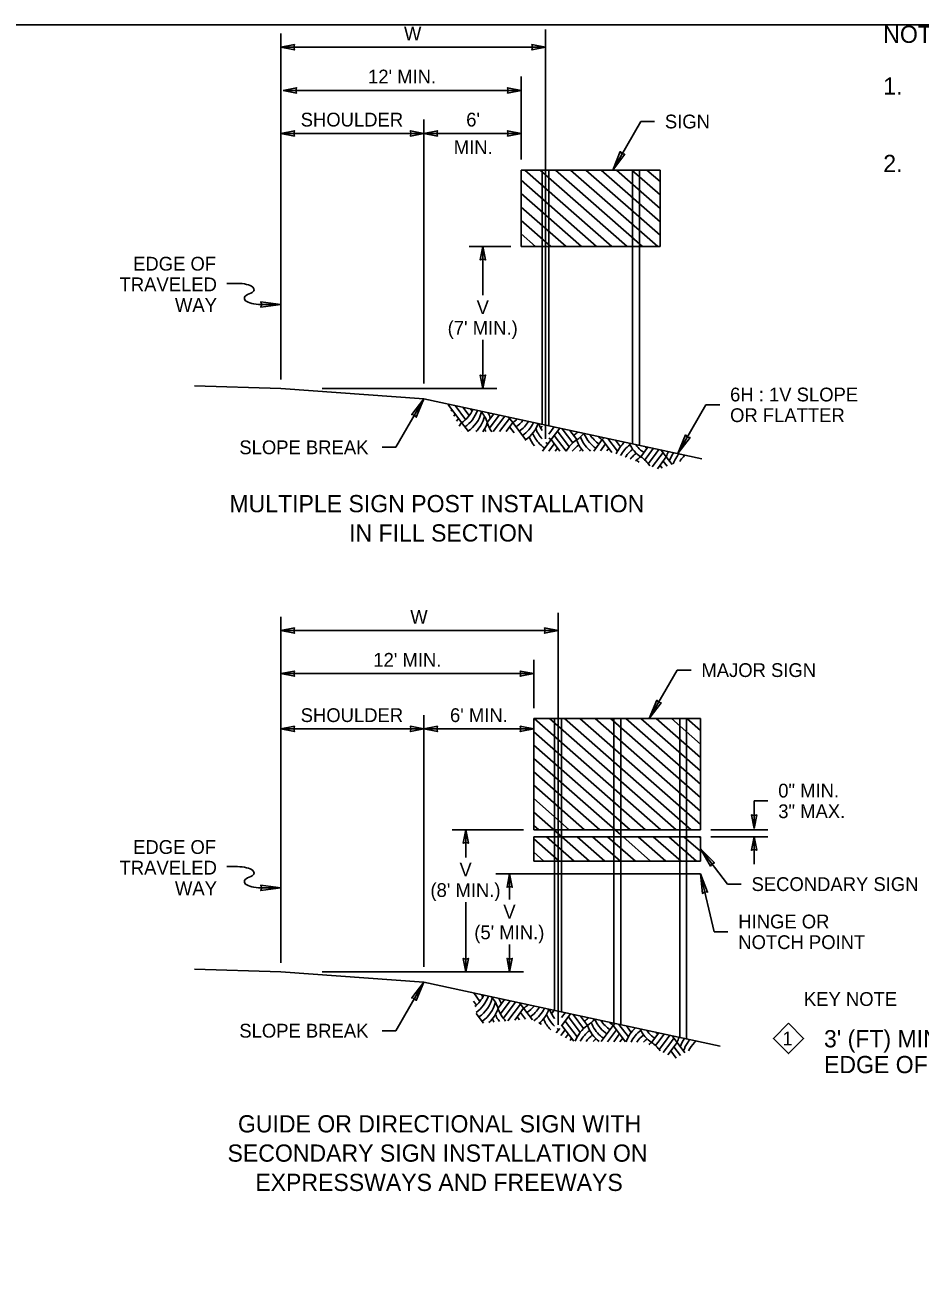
# Model space of a CAD drawing. Extents: x 99862 to 104211, y 98939 to 102076.
# Drawn here: x 101570 to 102609, y 100631 to 102076 of the extents above; entities that cross this region are included whole.
import ezdxf

# ---------------------------------------------------------------- set-up
doc = ezdxf.new("R2010")
doc.units = 0
for name, color, linetype in [('Level 1', 7, 'Continuous'), ('Level 14', 7, 'Continuous'), ('Level 15', 7, 'Continuous'), ('Level 2', 7, 'Continuous'), ('Level 20', 7, 'Continuous'), ('Level 6', 7, 'Continuous')]:
    doc.layers.add(name, color=color, linetype=linetype)

msp = doc.modelspace()

# ---------------------------------------------------------------- linework, layer by layer
at = {"layer": 'Level 1'}
msp.add_lwpolyline([(99862, 99999.5), (103151, 99999.5), (103151, 102075.5), (99862, 102075.5)], close=True, dxfattribs=at)
msp.add_lwpolyline([(99862, 99999.5), (103151, 99999.5), (103151, 102075.5), (99862, 102075.5)], close=True, dxfattribs=at)
at = {"layer": 'Level 14'}
for p, q in [((101816.5, 101775.4), (101804.3, 101775.4)), ((101863, 101750.8), (101843.8, 101750.8)), ((101816.5, 101098.1), (101804.3, 101098.1)), ((101863, 101073.5), (101843.8, 101073.5))]:
    msp.add_line(p, q, dxfattribs=at)
for points in [[(101867.1, 101750.8), (101843.7, 101747.8), (101844.8, 101750.8), (101843.7, 101753.9)], [(101867.1, 101073.5), (101843.7, 101070.4), (101844.8, 101073.5), (101843.7, 101076.5)]]:
    msp.add_lwpolyline(points, close=True, dxfattribs=at)
for centre, start_param, end_param in [((101816.7, 101768.2), 5.497747, 7.861127), ((101843.8, 101758), 2.356226, 4.712389), ((101816.7, 101090.9), 5.497747, 7.861127), ((101843.8, 101080.7), 2.356226, 4.712389)]:
    msp.add_ellipse(centre, major_axis=(19.2, 0), ratio=0.375, start_param=start_param, end_param=end_param, dxfattribs=at)
at = {"layer": 'Level 15'}
for p, q in [((101867.1, 102065.5), (101867.1, 101663.8)), ((102174.2, 102049.5), (101867.1, 102049.5)), ((102145.9, 102015.5), (102145.9, 101919)), ((102145.9, 101999.5), (101869.5, 101999.5)), ((102033, 101965.5), (102033, 101659.1)), ((102252.2, 101907), (102284.7, 101963.3)), ((102284.7, 101963.3), (102300.7, 101963.3)), ((102033, 101949.5), (101867.1, 101949.5)), ((102145.9, 101949.5), (102033, 101949.5)), ((102085.6, 101818.3), (102133.9, 101818.3)), ((102101.6, 101818.3), (102101.6, 101761.7)), ((102101.6, 101709.7), (102101.6, 101653.1)), ((101915.1, 101653.1), (102117.6, 101653.1)), ((102033, 101641.3), (102000.5, 101585)), ((102327.9, 101578), (102360.4, 101634.3)), ((102360.4, 101634.3), (102376.4, 101634.3)), ((101984.5, 101585), (102000.5, 101585)), ((101867.1, 101388.2), (101867.1, 100986.5)), ((102188.8, 101372.2), (101867.1, 101372.2)), ((102160.5, 101338.2), (102160.5, 101282)), ((102160.5, 101322.2), (101867.1, 101322.2)), ((102294.6, 101270), (102327.1, 101326.3)), ((102327.1, 101326.3), (102343.1, 101326.3)), ((102033, 101274), (102033, 100981.8)), ((102033, 101258), (101867.1, 101258)), ((102160.5, 101258), (102033, 101258)), ((102416.3, 101142.4), (102416.3, 101174.4)), ((102416.3, 101174.4), (102432.3, 101174.4)), ((102065.7, 101140.9), (102148.5, 101140.9)), ((102081.7, 101140.9), (102081.7, 101108.9)), ((102366.1, 101140.9), (102432.3, 101140.9)), ((102366.1, 101132.9), (102432.3, 101132.9)), ((102416.3, 101100.9), (102416.3, 101132.9)), ((102385.3, 101077.8), (102354.1, 101118.8)), ((102132.5, 101089.9), (102132.5, 101059.8)), ((102369.9, 101022.4), (102354, 101089.9)), ((102385.3, 101077.8), (102401.3, 101077.8)), ((102081.7, 101056.9), (102081.7, 100975.8)), ((102369.9, 101022.4), (102385.9, 101022.4)), ((102132.5, 101007.8), (102132.5, 100975.8)), ((101915.1, 100975.8), (102148.5, 100975.8)), ((102033, 100963.9), (102000.5, 100907.6)), ((101984.5, 100907.6), (102000.5, 100907.6))]:
    msp.add_line(p, q, dxfattribs=at)
for points in [[(101867.1, 102049.5), (101882.8, 102046.4), (101882.1, 102049.5), (101882.8, 102052.6)], [(102174.2, 102049.5), (102158.4, 102046.4), (102159.2, 102049.5), (102158.4, 102052.6)], [(101869.5, 101999.5), (101885.2, 101996.4), (101884.5, 101999.5), (101885.2, 102002.6)], [(102145.9, 101999.5), (102130.2, 101996.4), (102130.9, 101999.5), (102130.2, 102002.6)], [(101867.1, 101949.5), (101882.8, 101946.4), (101882.1, 101949.5), (101882.8, 101952.6)], [(102033, 101949.5), (102017.3, 101946.4), (102018, 101949.5), (102017.3, 101952.6)], [(102033, 101949.5), (102048.7, 101946.4), (102048, 101949.5), (102048.7, 101952.6)], [(102145.9, 101949.5), (102130.2, 101946.4), (102130.9, 101949.5), (102130.2, 101952.6)], [(102252.2, 101907), (102261, 101928.3), (102263.1, 101925.9), (102266.2, 101925.3)], [(102101.6, 101818.3), (102098.5, 101802.6), (102101.6, 101803.3), (102104.7, 101802.6)], [(102101.6, 101653.1), (102098.5, 101668.8), (102101.6, 101668.1), (102104.7, 101668.8)], [(102033, 101641.3), (102024.2, 101620), (102022.1, 101622.4), (102019, 101623)], [(102327.9, 101578), (102336.7, 101599.3), (102338.8, 101596.9), (102341.9, 101596.3)], [(101867.1, 101372.2), (101882.8, 101369.1), (101882.1, 101372.2), (101882.8, 101375.2)], [(102188.8, 101372.2), (102173.1, 101369.1), (102173.8, 101372.2), (102173.1, 101375.2)], [(101867.1, 101322.2), (101882.8, 101319.1), (101882.1, 101322.2), (101882.8, 101325.2)], [(102160.5, 101322.2), (102144.8, 101319.1), (102145.5, 101322.2), (102144.8, 101325.2)], [(102294.6, 101270), (102303.4, 101291.3), (102305.5, 101288.9), (102308.6, 101288.3)], [(101867.1, 101258), (101882.8, 101254.9), (101882.1, 101258), (101882.8, 101261.1)], [(102033, 101258), (102017.3, 101254.9), (102018, 101258), (102017.3, 101261.1)], [(102033, 101258), (102048.7, 101254.9), (102048, 101258), (102048.7, 101261.1)], [(102160.5, 101258), (102144.8, 101254.9), (102145.5, 101258), (102144.8, 101261.1)], [(102416.3, 101142.4), (102413.2, 101158.2), (102416.3, 101157.4), (102419.4, 101158.2)], [(102081.7, 101140.9), (102078.6, 101125.2), (102081.7, 101126), (102084.7, 101125.2)], [(102416.3, 101132.9), (102413.2, 101117.2), (102416.3, 101117.9), (102419.4, 101117.2)], [(102354.1, 101118.8), (102365.6, 101098.8), (102367.3, 101101.4), (102370.3, 101102.4)], [(102132.5, 101089.9), (102129.5, 101074.2), (102132.5, 101074.9), (102135.6, 101074.2)], [(102354, 101089.9), (102356.3, 101067), (102359, 101068.7), (102362.2, 101068.4)], [(102081.7, 100975.8), (102078.6, 100991.5), (102081.7, 100990.8), (102084.7, 100991.5)], [(102132.5, 100975.8), (102129.5, 100991.5), (102132.5, 100990.8), (102135.6, 100991.5)], [(102033, 100963.9), (102024.2, 100942.7), (102022.1, 100945.1), (102019, 100945.6)]]:
    msp.add_lwpolyline(points, close=True, dxfattribs=at)
at = {"layer": 'Level 2'}
for p, q in [((102174.2, 102070.3), (102174.2, 101594.8)), ((102145.9, 101907), (102145.9, 101818.3)), ((102145.9, 101907), (102307.3, 101907)), ((102251.2, 101818.3), (102150.1, 101907)), ((102268.9, 101818.3), (102167.8, 101907)), ((102170.1, 101818.3), (102170.1, 101907)), ((102178.2, 101818.3), (102178.2, 101907)), ((102286.6, 101818.3), (102185.6, 101907)), ((102304.4, 101818.3), (102203.3, 101907)), ((102307.3, 101831.3), (102221, 101907)), ((102307.3, 101846.9), (102238.7, 101907)), ((102307.3, 101862.4), (102256.5, 101907)), ((102307.3, 101878), (102274.2, 101907)), ((102275, 101818.3), (102275, 101907)), ((102283.1, 101818.3), (102283.1, 101907)), ((102307.3, 101893.5), (102291.9, 101907)), ((102307.3, 101907), (102307.3, 101818.3)), ((102233.5, 101818.3), (102145.9, 101895.1)), ((102215.8, 101818.3), (102145.9, 101879.6)), ((102198.1, 101818.3), (102145.9, 101864)), ((102180.3, 101818.3), (102145.9, 101848.5)), ((102162.6, 101818.3), (102145.9, 101832.9)), ((102145.9, 101818.3), (102307.3, 101818.3)), ((102170.1, 101818.3), (102170.1, 101611.6)), ((102178.2, 101818.3), (102178.2, 101609.9)), ((102275, 101818.3), (102275, 101589)), ((102283.1, 101818.3), (102283.1, 101587.2)), ((101867.1, 101653.1), (101766.6, 101656.2)), ((101867.1, 101653.1), (102033, 101641.3)), ((102033, 101641.3), (102355.7, 101571.5)), ((102275.5, 101588.9), (102275, 101589.3)), ((102188.8, 101393), (102188.8, 100914.3)), ((102160.5, 101270), (102160.5, 101140.9)), ((102160.5, 101270), (102354.1, 101270)), ((102308, 101140.9), (102161, 101270)), ((102325.7, 101140.9), (102178.7, 101270)), ((102184.7, 101140.9), (102184.7, 101270)), ((102192.8, 101140.9), (102192.8, 101270)), ((102343.4, 101140.9), (102196.4, 101270)), ((102354.1, 101147.1), (102214.1, 101270)), ((102354.1, 101162.7), (102231.9, 101270)), ((102354.1, 101178.2), (102249.6, 101270)), ((102253.3, 101140.9), (102253.3, 101270)), ((102261.4, 101140.9), (102261.4, 101270)), ((102354.1, 101193.8), (102267.3, 101270)), ((102354.1, 101209.3), (102285, 101270)), ((102354.1, 101224.9), (102302.7, 101270)), ((102354.1, 101240.4), (102320.5, 101270)), ((102329.9, 101140.9), (102329.9, 101270)), ((102338, 101140.9), (102338, 101270)), ((102354.1, 101256), (102338.2, 101270)), ((102354.1, 101270), (102354.1, 101140.9)), ((102290.3, 101140.9), (102160.5, 101254.8)), ((102272.6, 101140.9), (102160.5, 101239.3)), ((102261.4, 101135.2), (102160.5, 101223.7)), ((102237.1, 101140.9), (102160.5, 101208.2)), ((102219.4, 101140.9), (102160.5, 101192.6)), ((102160.5, 101177.1), (102201.7, 101140.9)), ((102225.3, 101104.6), (102160.8, 101161.3)), ((102166.3, 101140.9), (102160.5, 101146)), ((102160.5, 101140.9), (102354.1, 101140.9)), ((102160.5, 101132.9), (102354.1, 101132.9)), ((102160.5, 101132.9), (102160.5, 101104.6)), ((102207.6, 101104.6), (102175.5, 101132.9)), ((102184.7, 101140.9), (102184.7, 101132.9)), ((102184.7, 101132.9), (102184.7, 101104.6)), ((102192.8, 101140.9), (102192.8, 101132.9)), ((102192.8, 101132.9), (102192.8, 101104.6)), ((102210.9, 101132.9), (102243, 101104.6)), ((102261.4, 101104.1), (102228.6, 101132.9)), ((102278.5, 101104.6), (102246.3, 101132.9)), ((102253.3, 101140.9), (102253.3, 101132.9)), ((102253.3, 101132.9), (102253.3, 101104.6)), ((102261.4, 101140.9), (102261.4, 101132.9)), ((102261.4, 101132.9), (102261.4, 101104.6)), ((102296.2, 101104.6), (102263.9, 101133)), ((102313.9, 101104.6), (102281.7, 101132.9)), ((102331.5, 101104.6), (102299.3, 101132.9)), ((102349.3, 101104.6), (102317.2, 101132.9)), ((102329.9, 101132.9), (102329.9, 101140.9)), ((102329.9, 101132.9), (102329.9, 101104.6)), ((102354.1, 101116), (102334.9, 101132.9)), ((102338, 101132.9), (102338, 101140.9)), ((102338, 101132.9), (102338, 101104.6)), ((102354.1, 101131.6), (102352.6, 101132.9)), ((102354.1, 101132.9), (102354.1, 101104.6)), ((102189.9, 101104.6), (102160.5, 101130.4)), ((102172.2, 101104.6), (102160.5, 101114.8)), ((102160.5, 101104.6), (102354.1, 101104.6)), ((102184.7, 101104.6), (102184.7, 100931.1)), ((102192.8, 101104.6), (102192.8, 100929.4)), ((102253.3, 101104.6), (102253.3, 100916.3)), ((102261.4, 101104.6), (102261.4, 100914.6)), ((102329.9, 100899.8), (102329.9, 101104.6)), ((102338, 100898), (102338, 101104.6)), ((102116.5, 101089.9), (102354, 101089.9)), ((101867.1, 100975.8), (101766.6, 100978.9)), ((101867.1, 100975.8), (102033, 100963.9)), ((102033, 100963.9), (102377, 100889.6))]:
    msp.add_line(p, q, dxfattribs=at)
msp.add_lwpolyline([(102033, 101641.3), (102031.2, 101639.4), (102031.7, 101639.2), (102032, 101638.9)], close=True, dxfattribs=at)
at = {"layer": 'Level 20'}
msp.add_lwpolyline([(102456.2, 100916.2), (102473.7, 100898.6), (102456.2, 100881.1), (102438.6, 100898.6)], close=True, dxfattribs=at)
at = {"layer": 'Level 6'}
for p, q in [((102061.4, 101632.8), (102061.9, 101633.5)), ((102061.9, 101633.5), (102062.9, 101634.8)), ((102061.9, 101633.5), (102076.8, 101613.7)), ((102064.5, 101627), (102065.6, 101628.5)), ((102067.6, 101621.2), (102069.4, 101623.6)), ((102069.4, 101633.4), (102081.4, 101617.3)), ((102078.3, 101631.5), (102085.5, 101621.8)), ((102087.1, 101629.6), (102089, 101627.1)), ((102106.5, 101613.7), (102114.1, 101623.8)), ((102109.2, 101607.3), (102120.4, 101622.4)), ((102070.7, 101615.4), (102073.1, 101618.6)), ((102073.8, 101609.6), (102076.8, 101613.7)), ((102076.8, 101613.7), (102084.6, 101603.2)), ((102113.5, 101603.2), (102126.8, 101621)), ((102120.9, 101603.2), (102132.5, 101618.6)), ((102128.4, 101603.2), (102136.2, 101613.7)), ((102131.4, 101620), (102136.2, 101613.7)), ((102132.5, 101608.7), (102137.6, 101601.9)), ((102136.2, 101613.7), (102151, 101593.9)), ((102140.3, 101618.1), (102140.8, 101617.3)), ((102168.5, 101607.3), (102170.2, 101609.5)), ((102178.2, 101600.3), (102184.3, 101608.6)), ((102077.1, 101603.3), (102077.2, 101603.2)), ((102128.8, 101603.8), (102129.2, 101603.2)), ((102170.7, 101580.5), (102180.7, 101593.9)), ((102180.7, 101593.9), (102190.7, 101607.2)), ((102180.7, 101593.9), (102190.7, 101580.5)), ((102184.4, 101598.8), (102198.1, 101580.5)), ((102188.1, 101603.8), (102201.7, 101585.7)), ((102193.4, 101606.6), (102205.8, 101590.2)), ((102202.3, 101604.7), (102210.4, 101593.9)), ((102230.3, 101580.7), (102240.1, 101593.9)), ((102240.1, 101593.9), (102241.8, 101596.1)), ((102240.1, 101593.9), (102251.3, 101578.9)), ((102246.6, 101595.1), (102257.6, 101580.4)), ((102255.5, 101593.2), (102261.1, 101585.7)), ((102178.1, 101580.4), (102184.4, 101588.9)), ((102185.5, 101580.5), (102188.1, 101584)), ((102237.8, 101580.8), (102243.8, 101588.9)), ((102245.2, 101580.8), (102247.5, 101584)), ((102251.2, 101579), (102251.3, 101579)), ((102264.3, 101591.3), (102265.2, 101590.2)), ((102284.7, 101574.1), (102293, 101585.1)), ((102292.1, 101574.1), (102299.3, 101583.7)), ((102299.5, 101574.1), (102305.7, 101582.3)), ((102306.9, 101574.1), (102310.7, 101579)), ((102308.6, 101581.7), (102314.4, 101574.1)), ((102289.3, 101570.4), (102292.1, 101574.1)), ((102293.4, 101565.9), (102299.5, 101574.1)), ((102298.1, 101562.3), (102306.9, 101574.1)), ((102304, 101560.2), (102314.4, 101574.1)), ((102306.9, 101564.2), (102309.5, 101560.7)), ((102310.7, 101569.1), (102315.3, 101563)), ((102314.4, 101574.1), (102321, 101565.2)), ((102090.9, 100951.4), (102098.1, 100941.7)), ((102099.7, 100949.5), (102101.6, 100947)), ((102119.1, 100933.6), (102126.7, 100943.7)), ((102090.6, 100941.9), (102094.1, 100937.3)), ((102121.8, 100927.2), (102133.1, 100942.3)), ((102125.2, 100921.9), (102139.5, 100940.9)), ((102130.5, 100919.1), (102145.1, 100938.5)), ((102138.5, 100919.8), (102148.8, 100933.6)), ((102144, 100939.9), (102148.8, 100933.6)), ((102145.1, 100928.6), (102150.9, 100920.9)), ((102148.8, 100933.6), (102158.9, 100920.1)), ((102152.9, 100938), (102153.5, 100937.3)), ((102181.2, 100927.2), (102184.2, 100931.3)), ((102192.8, 100922.9), (102197, 100928.5)), ((102093.8, 100927.7), (102102.2, 100916.5)), ((102141.4, 100923.7), (102143.9, 100920.3)), ((102184.6, 100921.9), (102184.8, 100922.1)), ((102193.3, 100913.8), (102203.3, 100927.1)), ((102197.1, 100918.7), (102210.9, 100900.3)), ((102200.8, 100923.7), (102214.3, 100905.6)), ((102206.1, 100926.5), (102218.4, 100910.1)), ((102214.9, 100924.6), (102223, 100913.8)), ((102252.7, 100913.8), (102254.5, 100916.1)), ((102259.2, 100915), (102270.3, 100900.3)), ((102186.7, 100905), (102190.7, 100910.3)), ((102192, 100902.1), (102197.1, 100908.8)), ((102192.8, 100913), (102193.3, 100913.8)), ((102193.3, 100913.8), (102207.1, 100895.5)), ((102197.3, 100899.3), (102200.8, 100903.9)), ((102238.6, 100894.9), (102252.7, 100913.8)), ((102246, 100894.8), (102256.5, 100908.8)), ((102252.7, 100913.8), (102267.2, 100894.5)), ((102253.3, 100894.7), (102260.2, 100903.9)), ((102268.1, 100913.1), (102273.7, 100905.6)), ((102276.9, 100911.2), (102277.8, 100910.1)), ((102297.3, 100894), (102305.6, 100905)), ((102304.7, 100894), (102312, 100903.6)), ((102312.1, 100894), (102318.4, 100902.3)), ((102321.2, 100901.6), (102327, 100894)), ((102202.6, 100896.4), (102204.5, 100898.9)), ((102260.6, 100894.6), (102263.9, 100898.9)), ((102301.9, 100890.3), (102304.7, 100894)), ((102306, 100885.8), (102312.1, 100894)), ((102310.8, 100882.3), (102319.6, 100894)), ((102316.1, 100879.4), (102327, 100894)), ((102319.6, 100894), (102323.3, 100898.9)), ((102323.3, 100889), (102330.9, 100878.9)), ((102327, 100894), (102336, 100881.9)), ((102319.6, 100884.1), (102325.7, 100875.9))]:
    msp.add_line(p, q, dxfattribs=at)
for centre, start, end in [((102026.1, 101622.1), 17.6434, 20.3714), ((102055.8, 101644.8), 303.9036, 335.0285), ((102059.5, 101639.9), 303.9036, 341.3015), ((102063.2, 101634.9), 303.9036, 346.3199), ((102070.7, 101602.3), 17.6434, 41.2116), ((102074.4, 101607.2), 17.6434, 28.5946), ((102078.1, 101612.2), 17.6434, 18.0482), ((102067, 101630), 314.5626, 345.7713), ((102070.7, 101625), 324.4958, 342.3566), ((102142.3, 101625), 197.6435, 215.5042), ((102115.2, 101644.8), 303.9036, 314.095), ((102118.9, 101639.9), 303.9036, 321.2471), ((102122.6, 101634.9), 303.9036, 327.9759), ((102126.4, 101630), 303.9036, 334.4296), ((102130.1, 101625), 303.9036, 340.7141), ((102201.7, 101625), 199.5436, 213.0044), ((102138.6, 101620.1), 200.8778, 206.6822), ((102172, 101562.7), 123.9036, 124.773), ((102186.8, 101605.2), 197.6434, 198.9177), ((102190.5, 101610.2), 200.2432, 218.8345), ((102194.3, 101615.1), 201.4344, 220.9416), ((102198, 101620.1), 200.8778, 211.332), ((102198, 101620.1), 211.3319, 222.2824), ((102201.7, 101625), 231.2638, 236.0964), ((102231.4, 101562.7), 123.9036, 151.5955), ((102182, 101634.9), 303.9036, 305.5014), ((102185.8, 101630), 303.9036, 313.3908), ((102189.5, 101625), 303.9036, 320.593), ((102246.2, 101605.2), 197.6434, 220.8447), ((102249.9, 101610.2), 200.2432, 228.9599), ((102253.7, 101615.1), 201.9061, 220.9416), ((102257.4, 101620.1), 213.0611, 236.0964), ((102261.1, 101625), 227.1068, 236.0964), ((102194.3, 101615.1), 220.9415, 236.0964), ((102198, 101620.1), 231.3025, 236.0964), ((102235.1, 101557.7), 126.3063, 142.5106), ((102238.8, 101552.8), 127.1006, 132.1171), ((102253.7, 101615.1), 220.9415, 236.0964), ((102249.9, 101610.2), 228.9599, 231.6474), ((102290.8, 101562.7), 131.2418, 157.2165), ((102294.5, 101557.7), 126.3063, 151.9674), ((102298.2, 101552.8), 127.1006, 145.4911), ((102305.6, 101605.2), 204.3362, 236.0964), ((102309.3, 101610.2), 215.9529, 228.9599), ((102309.3, 101610.2), 228.9599, 236.0964), ((102313.1, 101615.1), 231.2457, 236.0964), ((102350.2, 101562.7), 152.6241, 162.3566), ((102353.9, 101557.7), 146.1046, 154.2266), ((102298.2, 101552.8), 145.491, 146.6452), ((102301.9, 101547.8), 135.7127, 141.1981), ((102301.9, 101547.8), 126.331, 135.7128), ((102305.6, 101542.9), 123.9036, 135.5629), ((102260, 101537.9), 52.5056, 58.5465), ((102263.7, 101542.9), 33.0354, 56.0963), ((102353.9, 101557.7), 154.2265, 162.3566), ((102357.6, 101552.8), 145.491, 159.924), ((102357.6, 101552.8), 139.2736, 145.4911), ((102361.3, 101547.8), 135.7127, 146.3364), ((102361.3, 101547.8), 131.9647, 135.7128), ((102068.4, 100964.8), 308.8907, 335.025), ((102072.2, 100959.8), 304.6478, 341.2982), ((102075.9, 100954.9), 303.9036, 346.3199), ((102083.3, 100922.2), 17.6434, 41.2062), ((102087, 100927.1), 17.6434, 28.5904), ((102090.7, 100932.1), 17.6434, 18.0447), ((102079.6, 100949.9), 303.9036, 345.7713), ((102083.3, 100945), 312.0393, 342.3566), ((102154.9, 100945), 197.6435, 224.0758), ((102127.8, 100964.8), 303.9036, 314.0918), ((102131.6, 100959.8), 303.9036, 321.2442), ((102135.3, 100954.9), 303.9036, 327.9732), ((102139, 100949.9), 305.111, 334.4271), ((102142.7, 100945), 309.4244, 340.7117), ((102214.3, 100945), 199.5464, 218.1923), ((102143.8, 100930.1), 200.2432, 200.3238), ((102147.5, 100935.1), 201.4344, 207.7286), ((102151.2, 100940), 200.8778, 211.332), ((102151.2, 100940), 211.3319, 215.5572), ((102203.2, 100930.1), 200.2432, 204.3027), ((102206.9, 100935.1), 201.4344, 220.9416), ((102210.6, 100940), 200.8778, 211.332), ((102210.6, 100940), 211.3319, 226.5951), ((102214.3, 100945), 235.0371, 236.0964), ((102194.7, 100954.9), 303.9036, 305.4989), ((102198.4, 100949.9), 303.9036, 313.3887), ((102202.1, 100945), 303.9036, 320.5911), ((102262.6, 100930.1), 200.2432, 228.9599), ((102266.3, 100935.1), 201.9081, 220.9416), ((102270, 100940), 213.0633, 236.0964), ((102273.7, 100945), 227.1096, 236.0964), ((102206.9, 100935.1), 220.9415, 225.121), ((102210.6, 100940), 232.3618, 236.0964), ((102244, 100882.6), 123.9036, 160.0249), ((102247.7, 100877.6), 126.3063, 151.9131), ((102251.4, 100872.7), 127.1006, 143.1576), ((102258.9, 100925.2), 197.6434, 233.4547), ((102266.3, 100935.1), 220.9415, 236.0964), ((102262.6, 100930.1), 228.9599, 236.0964), ((102303.4, 100882.6), 131.2431, 161.5631), ((102307.1, 100877.6), 126.3063, 153.543), ((102310.8, 100872.7), 127.1006, 144.9412), ((102318.3, 100925.2), 204.3374, 236.0964), ((102322, 100930.1), 215.9542, 228.9599), ((102322, 100930.1), 228.9599, 236.0964), ((102325.7, 100935.1), 231.2473, 236.0964), ((102362.8, 100882.6), 152.6245, 162.3566), ((102255.1, 100867.7), 126.331, 133.2897), ((102314.5, 100867.7), 126.331, 135.3467), ((102318.3, 100862.8), 123.9036, 130.4273), ((102276.3, 100862.8), 34.7881, 56.0963), ((102366.5, 100877.6), 154.2265, 162.3566), ((102366.5, 100877.6), 146.1049, 154.2266), ((102370.2, 100872.7), 145.491, 162.3566), ((102370.2, 100872.7), 139.2738, 145.4911), ((102373.9, 100867.7), 135.7127, 153.7442), ((102373.9, 100867.7), 131.9648, 135.7128)]:
    msp.add_arc(centre, 37.6, start, end, dxfattribs=at)

# ---------------------------------------------------------------- texts
at = {"layer": 'Level 2'}
for s, p in [('MULTIPLE SIGN POST INSTALLATION', (101807.3, 101509.6)), ('IN FILL SECTION', (101946.2, 101475.6)), ('GUIDE OR DIRECTIONAL SIGN WITH', (101817.2, 100789.5)), ('SECONDARY SIGN INSTALLATION ON', (101805.1, 100755.5)), ('EXPRESSWAYS AND FREEWAYS', (101837.3, 100721.5))]:
    msp.add_text(s, height=20, dxfattribs=at).set_placement(p)
at = {"layer": 'Level 20'}
for s, height, p in [('W', 16, (102009.9, 102057.5)), ('NOTES', 20, (102566.2, 102054.6)), ("12' MIN.", 16, (101968.2, 102007.5)), ('1.', 20, (102566.2, 101994.6)), ('SHOULDER', 16, (101890, 101957.5)), ("6'", 16, (102082.1, 101957.5)), ('SIGN', 16, (102312.7, 101955.3)), ('MIN.', 16, (102067.7, 101925.5)), ('2.', 20, (102566.2, 101904.6)), ('EDGE OF', 16, (101695.5, 101790.2)), ('TRAVELED', 16, (101679.8, 101766.2)), ('WAY', 16, (101744.1, 101742.2)), ('V', 16, (102094.2, 101739.7)), ("(7' MIN.)", 16, (102060.6, 101715.7)), ('6H : 1V SLOPE', 16, (102388.4, 101638.3)), ('OR FLATTER', 16, (102388.4, 101614.3)), ('SLOPE BREAK', 16, (101818.8, 101577)), ('W', 16, (102017.2, 101380.2)), ("12' MIN.", 16, (101974.3, 101330.2)), ('MAJOR SIGN', 16, (102355.1, 101318.3)), ('SHOULDER', 16, (101890, 101266)), ("6' MIN.", 16, (102063.3, 101266)), ('0" MIN.', 16, (102444.3, 101178.4)), ('3" MAX.', 16, (102444.3, 101154.4)), ('EDGE OF', 16, (101695.5, 101112.9)), ('TRAVELED', 16, (101679.8, 101088.9)), ('V', 16, (102074.3, 101086.9)), ('WAY', 16, (101744.1, 101064.9)), ("(8' MIN.)", 16, (102040.6, 101062.9)), ('SECONDARY SIGN', 16, (102413.3, 101069.8)), ('V', 16, (102125.2, 101037.8)), ("(5' MIN.)", 16, (102091.5, 101013.8)), ('HINGE OR ', 16, (102397.9, 101026.4)), ('NOTCH POINT', 16, (102397.9, 101002.4)), ('KEY NOTE', 16, (102474.1, 100936.4)), ('SLOPE BREAK', 16, (101818.8, 100899.6)), ('1', 16, (102449.2, 100890.6)), ("3' (FT) MIN. FROM ANY POINT ALONG BOTTOM ", 20, (102497.4, 100888.3)), ('EDGE OF SIGN PANEL TO THE GROUND', 20, (102497.4, 100858.3))]:
    msp.add_text(s, height=height, dxfattribs=at).set_placement(p)

doc.saveas('drawing.dxf')
